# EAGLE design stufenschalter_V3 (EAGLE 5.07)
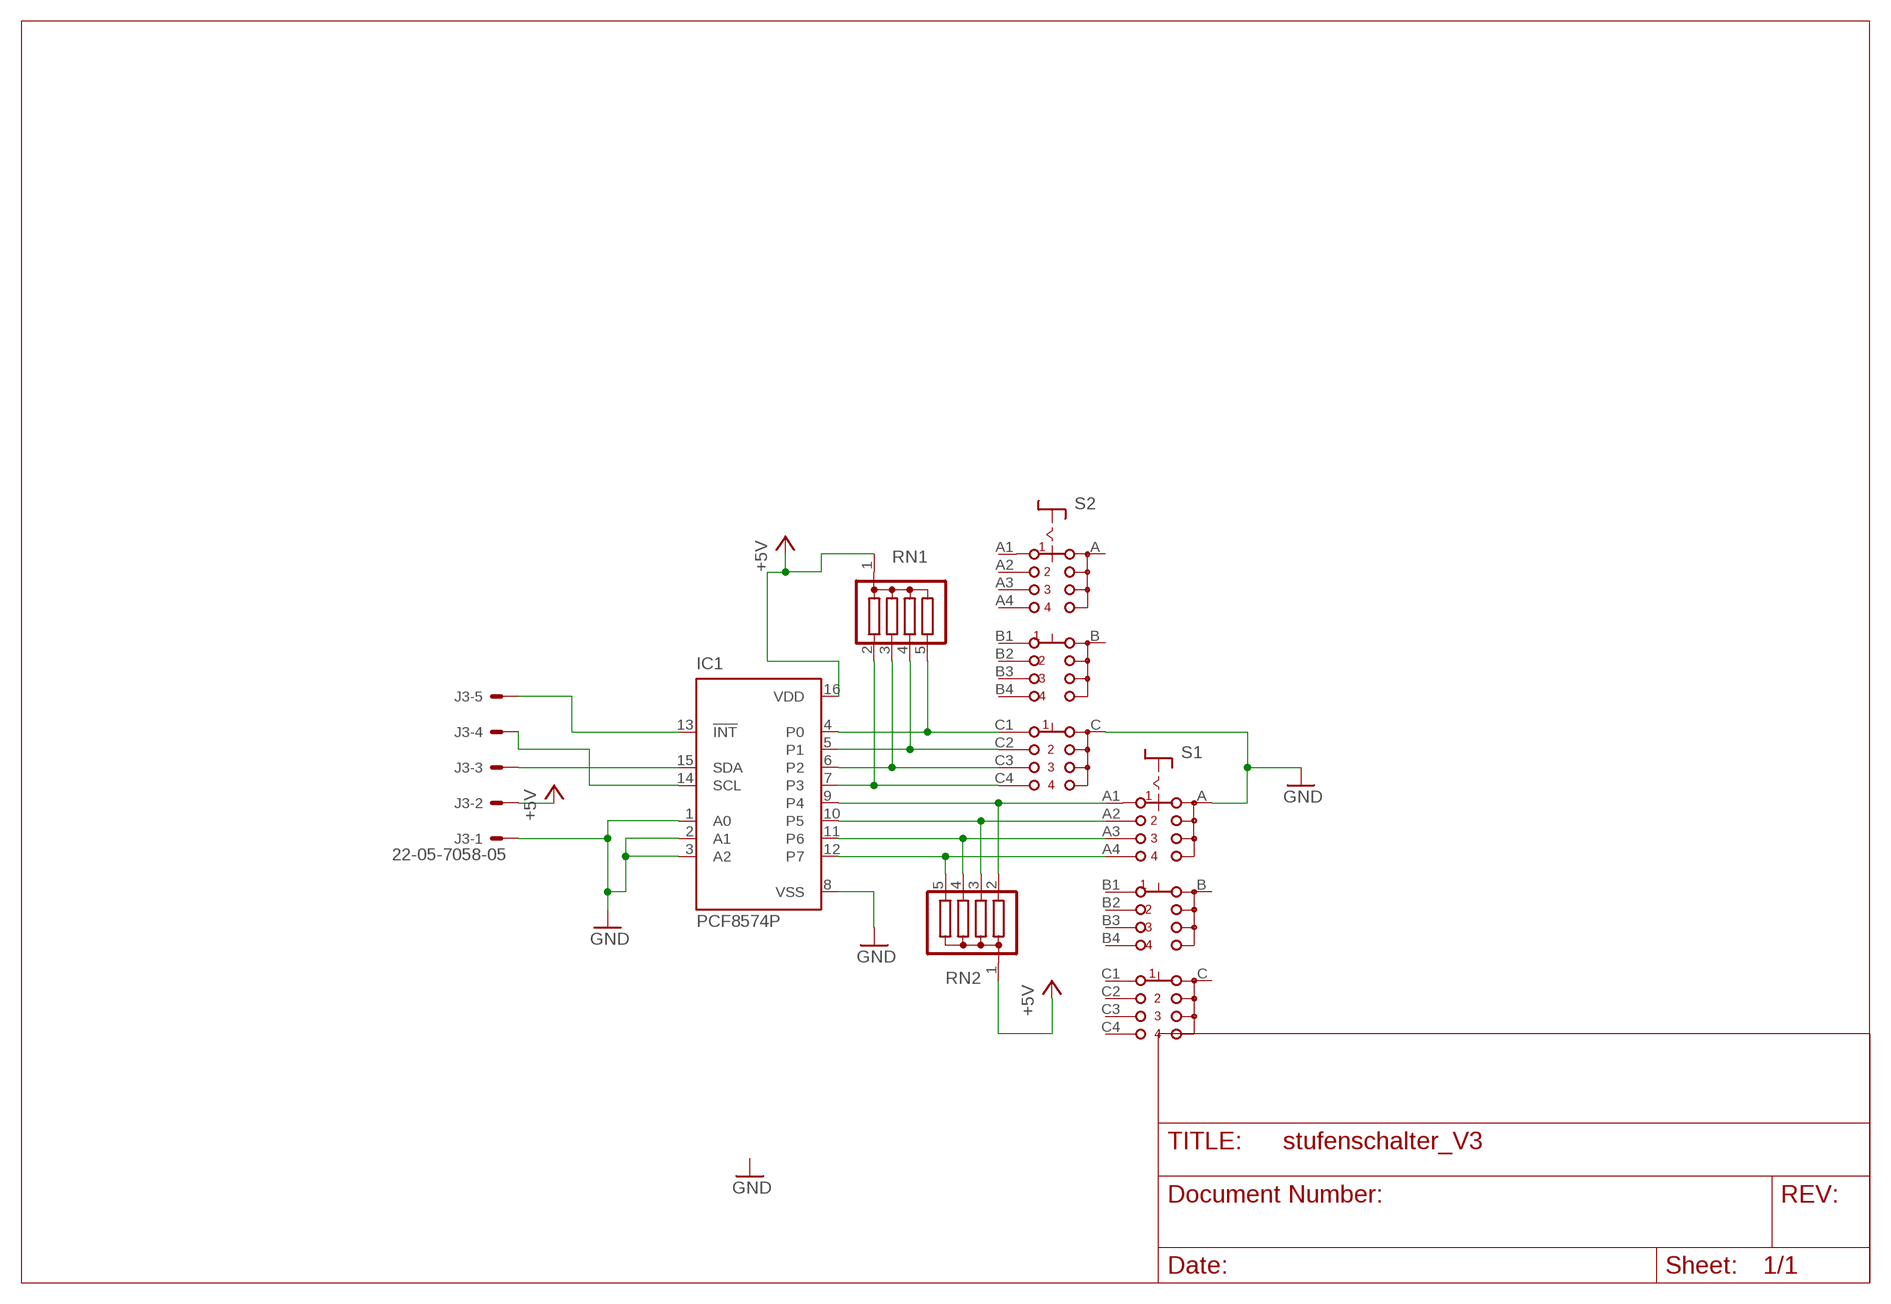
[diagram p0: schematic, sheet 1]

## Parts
IC1  PCF8574P  [DIL16]
J3  22-05-7058-05  [7395-05]
RN1  G04R  [SIL5]
RN2  G04R  [SIL5]
S1  CK103X04  [CK103X04]
S2  CK103X04  [CK103X04]

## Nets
+5V: IC1.16(VDD) J3.2 RN1.1 RN2.1
GND: IC1.1(A0) IC1.2(A1) IC1.3(A2) IC1.8(VSS) J3.1 S1.A S2.C
N$2: IC1.4(P0) RN1.5 S2.C1
N$3: IC1.5(P1) RN1.4 S2.C2
N$4: IC1.6(P2) RN1.3 S2.C3
N$5: IC1.7(P3) RN1.2 S2.C4
N$6: IC1.15(SDA) J3.3
N$7: IC1.13(!INT) J3.5
N$9: IC1.12(P7) RN2.5 S1.A4
N$12: IC1.14(SCL) J3.4
N$14: IC1.9(P4) RN2.2 S1.A1
N$15: IC1.10(P5) RN2.3 S1.A2
N$16: IC1.11(P6) RN2.4 S1.A3
Unconnected: S1.B S1.B1 S1.B2 S1.B3 S1.B4 S1.C S1.C1 S1.C2 S1.C3 S1.C4 S2.A S2.A1 S2.A2 S2.A3 S2.A4 S2.B S2.B1 S2.B2 S2.B3 S2.B4

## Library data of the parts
IC1 = micro-philips:PCF8574: I2C-Bus Remote 8-bit I/O expander http://www.semiconductors.philips.com/acrobat_download/datasheets/PCF8574_4.pdf
J3 = con-molex:22-?-05: CONNECTOR wire to board 2.54 mm (.1 inch) pitch header
RN1 RN2 = resistor-sil:G04R: SIL RESISTOR
S1 S2 = switch:CK103X04: ROTARY SWITCH C&K

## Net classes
0 default: width 0.813 mm, clearance 0.711 mm

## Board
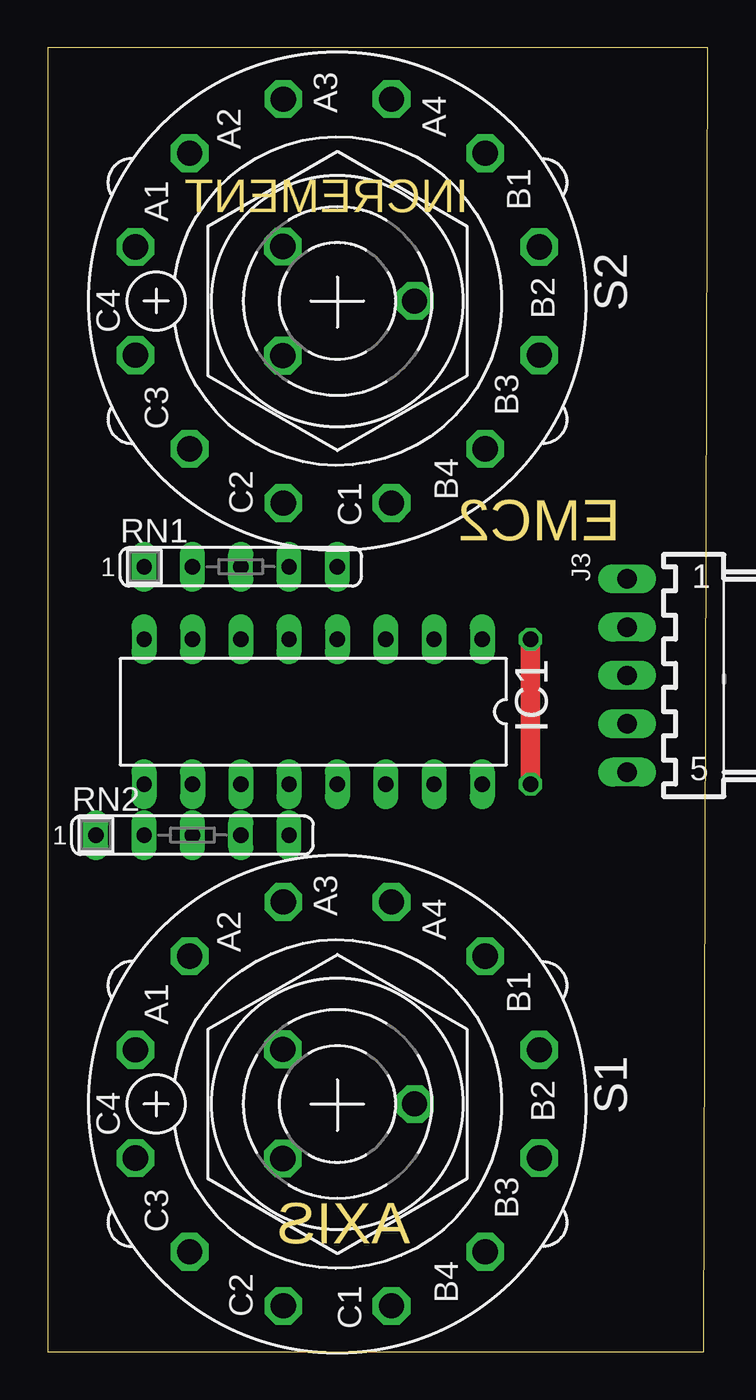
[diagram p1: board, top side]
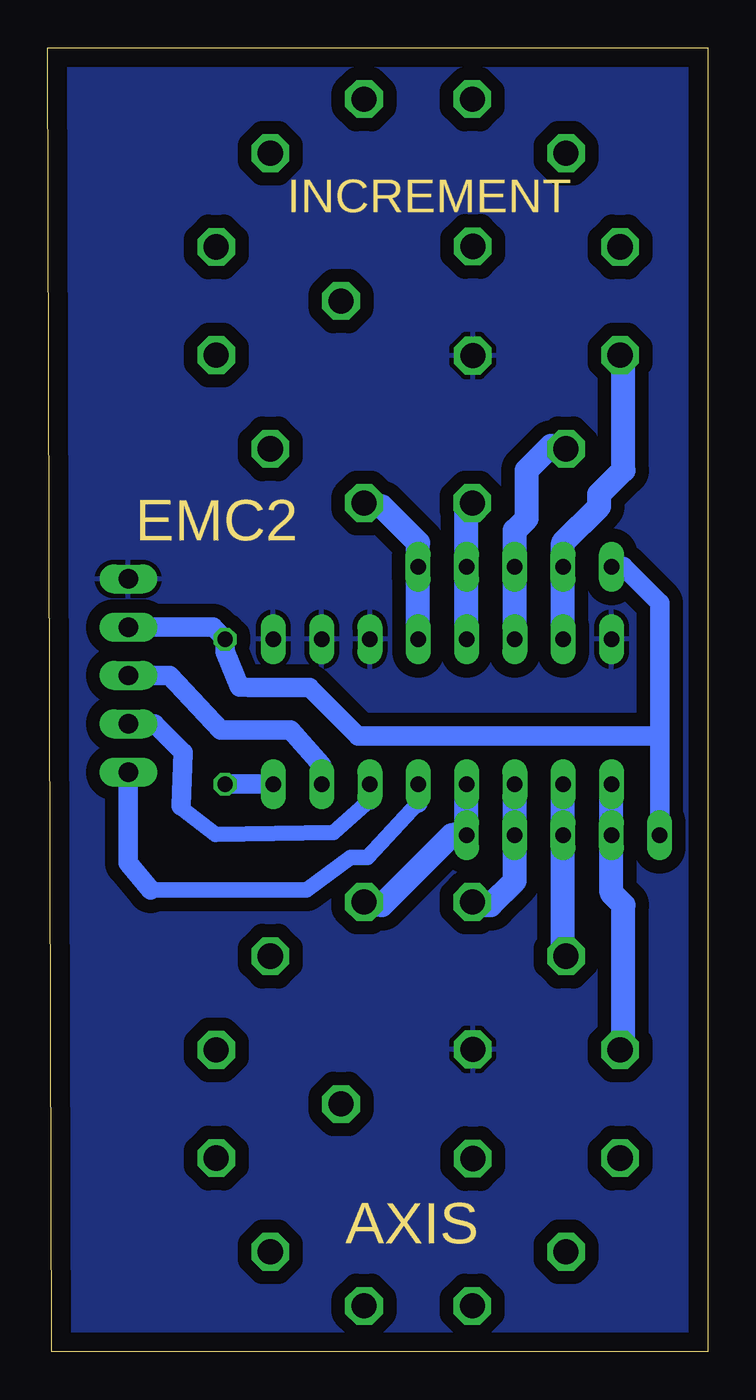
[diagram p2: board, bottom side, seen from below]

Size 34.73 x 68.57 mm. Coordinates in mm from the lower left corner, seen from the top.
Outline: 0,0 34.5,0 34.73,68.57 0,68.57 0,0
Copper layers (1*16): Top 0.035mm / dielectric 1.5mm / Bottom 0.035mm
Design rules "default": minimum track width 10mil, minimum drill 24mil, track to track 8mil, track to pad 8mil, pad to pad 8mil, via to via 8mil, smd to smd 8mil, copper to edge 40mil, drill to drill 8mil, minimum pad ring 10mil, minimum via ring 8mil, stop-mask expansion 4mil, vias tented up to drill 0mil, thermal gap 10mil

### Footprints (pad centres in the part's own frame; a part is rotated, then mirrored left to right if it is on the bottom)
DIL16 = drill 0.813 long: 1 -8.89,-3.81; 2 -6.35,-3.81; 3 -3.81,-3.81; 4 -1.27,-3.81; 5 1.27,-3.81; 6 3.81,-3.81; 7 6.35,-3.81; 8 8.89,-3.81; 9 8.89,3.81; 10 6.35,3.81; 11 3.81,3.81; 12 1.27,3.81; 13 -1.27,3.81; 14 -3.81,3.81; 15 -6.35,3.81; 16 -8.89,3.81
7395-05 = drill 1.016 long: 1 5.08,0; 2 2.54,0; 3 0,0; 4 -2.54,0; 5 -5.08,0
SIL5 = drill 0.813 long: 1 -5.08,0; 2 -2.54,0; 3 0,0; 4 2.54,0; 5 5.08,0
CK103X04 = drill 1.321 octagon: A -2.87,-2.87; A1 -2.845,-10.617; A2 -7.772,-7.772; A3 -10.617,-2.845; A4 -10.617,2.845; B 0,4.059; B1 -7.772,7.772; B2 -2.845,10.617; B3 2.845,10.617; B4 7.772,7.772; C 2.87,-2.87; C1 10.617,2.845; C2 10.617,-2.845; C3 7.772,-7.772; C4 2.845,-10.617

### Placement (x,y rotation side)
IC1  13.97,33.66 180 top
J3  30.48,35.56 90 top
RN1  10.16,41.27 0 top
RN2  7.62,27.17 0 top
S1  15.24,13.04 270 top
S2  15.24,55.24 270 top

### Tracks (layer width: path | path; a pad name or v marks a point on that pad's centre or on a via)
+5V  (via drill 0.8)
  Top 1.016: v25.4,37.47 v25.4,29.84
  Bottom 1.016: J3.2 26.04,38.1 v25.4,37.47 25.4,36.83 24.63,34.96 24.13,34.92 20.95,34.92 18.41,32.38 2.54,32.38 | v25.4,29.84 IC1.16 | 2.54,32.38 2.54,39.37 4.45,41.27 RN1.1 | RN2.1 2.54,32.38
GND
  pour Bottom (isolate 0.61): 0,68.58 34.83,68.58 34.33,0 0,0
N$2
  Bottom 1.27: IC1.4 RN1.5 15.24,42.55 17.14,44.45 17.91,44.45 S2.C1
N$3
  Bottom 1.27: IC1.5 RN1.4 12.7,44.32 S2.C2
N$4
  Bottom 1.27: IC1.6 RN1.3 10.16,43.18 9.53,43.81 9.53,46.35 8.26,47.62 7.62,47.62 S2.C3
N$5
  Bottom 1.27: IC1.7 RN1.2 7.62,42.55 5.71,44.45 5.71,45.09 4.45,46.35 4.45,52.22 S2.C4
N$6
  Bottom 1.016: J3.3 28.3,35.56 25.63,32.69 21.95,32.69 20.32,30.85 IC1.15
N$7
  Bottom 0.813: 15.24,28.86 17.9,26 18.8,26 21.1,24.3 29.3,24.3
  Bottom 1.016: IC1.13 15.24,28.86 | 29.3,24.3 30.5,25.7 30.5,30.46 J3.5
N$9
  Bottom 1.27: IC1.12 RN2.5 13.47,27.17 17.14,23.5 17.93,23.5 S1.A4
N$12
  Bottom 0.813: 17.78,29.02 19.7,27.3 25.9,27.2 27.7,28.6 27.7,28.7
  Bottom 1.016: 17.78,29.02 IC1.14 | 27.7,28.7 27.6,31.5 29.1,33 30.46,33 J3.4
N$14
  Bottom 1.27: IC1.9 RN2.2 5.08,24.13 4.45,23.5 4.45,16.06 S1.A1
N$15
  Bottom 1.27: IC1.10 RN2.3 7.62,20.96 S1.A2
N$16
  Bottom 1.27: IC1.11 RN2.4 10.16,24.77 11.43,23.5 12.24,23.5 S1.A3

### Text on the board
Milling: INCREMENT | EMC2 | AXIS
